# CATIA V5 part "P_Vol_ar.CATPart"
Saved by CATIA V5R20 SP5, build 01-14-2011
Part number: Vol_ar
Bounding box of the stored display mesh (mm): x -29.894 to 29.894, y 6.37 to 162.727, z -1098.664 to 0
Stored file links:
  U:\2A\CFAO\dossier sans titre\P_Vol_ar.CATPart
  U:\2A\CFAO\dossier sans titre\Gouvernail.CATProduct
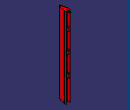
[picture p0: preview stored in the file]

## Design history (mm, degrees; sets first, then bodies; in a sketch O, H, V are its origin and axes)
External parameters (linked from other documents)
  External.Larg_Totale = 450 mm
  External.Long_Total = 1100 mm
Set1
  Point1 to Point5: linked copy from another document
Set2
  Plane1: type OffsetPt, RefPlane zx-plane, RefPoint Point2
  Plane2: type Offset, RefPlane Plane1, Offset 40 {= (40/450)*External.Larg_Totale}, reversed
  Plane3: type Offset, RefPlane xy-plane, Offset 215 {= External.Long_Total /4-60mm}, reversed
Body1 (main body)
  Sketch1 "Esquisse_trans" on xy-plane, origin (0, 0, 0), H (1, 0, 0), V (0, 1, 0)
    axis line L1 (0, 419.9562) -> (0, -126.2595)
    construction arc A1 centre (0, 415) radius 35 from (-34.4998, 420.8959) to (34.4998, 420.8959) cw
    point P3 (0, 415)
    reference projected point E1 (0, 450) from Point1
    construction arc A2 centre (-803.3534, 277.7108) radius 850 from (34.4998, 420.8959) to (0, 0) cw
    construction arc A3 centre (803.3534, 277.7108) radius 850 from (-34.4998, 420.8959) to (0, 0) ccw
    point P8 (-29.2898, 106.8153)
    point P9 (29.2898, 106.8153)
    arc A4 centre (-803.3534, 277.7108) radius 850 from (2.8454, 8.3719) to (29.2898, 106.8153) ccw
    point P11 (29.2898, 106.8153)
    point P12 (22.3611, 75.9796)
    arc A5 centre (803.3534, 277.7108) radius 850 from (-29.2898, 106.8153) to (-2.8454, 8.3719) ccw
    point P14 (-29.2898, 106.8153)
    point P15 (0, 0)
    reference projected point E2 (0, 0) from Point3
    arc A6 centre (0, 9.3225) radius 3 from (2.8454, 8.3719) to (-2.8454, 8.3719) cw
    arc A7 centre (0, 112.8269) radius 29.9004 from (29.2898, 106.8153) to (-29.2898, 106.8153) ccw
    point P19 (0, 112.8269)
    point P20 (29.2898, 106.8153)
    point P21 (-29.2898, 106.8153)
    reference projected point E3 (0, 142.7273) from Point2
    radius A2 = 850 {= (850/450)*External.Larg_Totale}
    radius A3 = 850 {= (850/450)*External.Larg_Totale}
    radius A1 = 35 {= (35/450)*External.Larg_Totale}
    radius A6 = 3
    coincidence: L1 V, P3 L1, A1 E1, P8 A3, P9 A2, P11 A2, A4 P12, P12 A2, P9 P11, P14 A3, P15 E2, A5 A3, O P15, P8 P14, A4 O, A5 P15, P20 A2, P21 A3, P19 L1, A7 E3, P20 P9, P21 P8
    tangency: A2 A1, A3 A1, A6 A4, A6 A5, A7 A4
  Sketch2 "Esquisse_long" on yz-plane, origin (0, 0, 0), H (0, 1, 0), V (0, 0, 1)
    point P1 (0, -1098.6638)
    line L1 (0, -1098.6638) -> (0, 0)
    line L2 (0, 0) -> (142.7273, 0)
    point P2 (142.7273, 0)
    line L3 (142.7273, 0) -> (142.7273, -1098.6638)
    line L4 (0, -1098.6638) -> (142.7273, -1098.6638)
    reference projected point E1 (142.7273, 0) from Point2
    coincidence: P1 V, P2 E1
    vertical: L1 V, L3 V
    horizontal: L2 H, L4 H
    perpendicularity: L4 L3, L2 L3
  SolidCombine1: FirstComponentDirection Sketch1, FirstComponentProfile Sketch1, SecondComponentDirection Sketch2, SecondComponentProfile Sketch2
  Sketch3 on Plane1, origin (0, 142.7273, 0), H (-1, 0, 0), V (0, 0, 1)
    line L1 (-5, 0) -> (5, 0)
    line L2 (5, 0) -> (5, -10)
    line L3 (5, -10) -> (-5, -10)
    line L4 (-5, 0) -> (-5, -10)
    length L1 = 10
    distance L2 V = 5 {= Sketch3.length(L1) /2}
    length L2 = 10
    horizontal: L1 H, L3 H
    vertical: L2 V, L4 V
    coincidence: L1 H
  Pad1 "Extrusion_bras_ar": profile Sketch3, direction (0, 1, 0), length 20 {= (20/450)*External.Larg_Totale}, opposite side length 2
  Sketch4 on Plane1, origin (0, 142.7273, 0), H (-1, 0, 0), V (0, 0, 1)
    line L1 (-4, -1) -> (4, -1)
    line L2 (4, -1) -> (4, -9)
    line L3 (4, -9) -> (-4, -9)
    line L4 (-4, -9) -> (-4, -1)
    length L2 = 8
    length L1 = 8
    distance L4 V = 4 {= Sketch4.length(L1) /2}
    distance L1 H = 1
    horizontal: L1 H, L3 H
    vertical: L2 V, L4 V
  Pocket1 "Poche_bras_ar": profile Sketch4, direction (0, -1, 0), length 40, opposite side length 20 {= (20/450)*External.Larg_Totale}
  Sketch5 on Plane1, origin (0, 142.7273, 0), H (-1, 0, 0), V (0, 0, 1)
    line L1 (-25, -15) -> (25, -15)
    line L2 (25, -15) -> (25, -1100)
    line L3 (25, -1100) -> (-25, -1100)
    line L4 (-25, -1100) -> (-25, -15)
    reference projected point E1 (0, -1100) from Point4
    distance L1 H = 15
    distance L2 V = 25 {= Sketch5.length(L1) /2}
    length L1 = 50
    horizontal: L1 H, L3 H
    vertical: L2 V, L4 V
    coincidence: L3 E1
  Pocket2 "Poche_rainure": profile Sketch5, direction (0, -1, 0), length 45 {= (45/450)*External.Larg_Totale}
  Sketch6 on Plane2, origin (0, 102.7273, 0), H (-1, 0, 0), V (0, 0, 1)
    circle A1 centre (0, -215) radius 12
    point P1 (0, -215)
    distance P1 H = 215 {= External.Long_Total /4-60mm}
    radius A1 = 12
    coincidence: P1 V
  Pad2 "Extrusion_charniere_1": profile Sketch6, direction (0, 1, 0), length 25 {= (25/450)*External.Larg_Totale}
  Sketch7 on Plane3, origin (0, 0, -215), H (1, 0, 0), V (0, 1, 0)
    circle A1 centre (0, 122.7273) radius 15
    point P1 (0, 122.7273)
    reference projected point E1 (0, 122.7273) from Point5
    radius A1 = 15
    coincidence: P1 E1
  Pad3 "Extrusion_charniere_2": profile Sketch7, direction (0, 0, -1), length 30, opposite side length 20
  Sketch8 on end face of Pad3, origin (0, 122.7273, -245), H (1, 0, 0), V (0, -1, 0)
    point P1 (0, 0)
  Hole1 "Trou_charniere": placed by Sketch8, at (0, 122.7273, -245) direction (0, 0, 1), diameter 8, depth 30
  Fillet1 "Congé_charniere": radius 3, on face of Pad3 from Sketch7.A1; face of Pad2 from Sketch6.A1; face of Hole1
  RectPattern1: of Pad2, Sketch6, Pad3, Sketch7, Hole1, Fillet1, direction 1 instances 3, spacing 275 {= External.Long_Total /4}, along Z axis reversed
